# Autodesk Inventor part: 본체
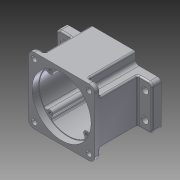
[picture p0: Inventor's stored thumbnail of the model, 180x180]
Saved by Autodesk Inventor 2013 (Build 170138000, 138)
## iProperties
Created: 2015-07
Part Number: 본체
Material: 알루미늄 6061
Document SubType Name: Modeling
Designer: user
Density: 2.71 g/cm^3
Mass: 705.328 g
Surface Area: 672.952 cm^2
Volume: 260.268 cm^3
Author: user
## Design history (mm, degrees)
sketch "스케치1"
  geometry: L1 (-45, 45)-(45, 45); L2 (45, 45)-(45, -45); L3 (45, -45)-(-45, -45); L4 (-45, -45)-(-45, 45); L5 (-45, 45)-(45, -45); L6 (45, 45)-(-45, -45); 1 further point
  constraints: 12 end point, 2 midpoint, 2 parallel, 1 horizontal, 1 perpendicular
  dimensions: "d0" = 90 distance of L2.end L3.end; "d1" = 90 distance of L1.end L2.end
extrude "돌출1" new body sketch "스케치1" distance "d2" = 58; taper "d3" = 0 deg
fillet "모깎기1" dims "d4" = 8
sketch "스케치3"
  geometry: L1 (-37, -45)-(37, -45) reference; L2 (45, -37)-(45, 37) reference; L3 (37, 45)-(-37, 45) reference; L4 (-45, 37)-(-45, -37) reference; L5 (-30, -45)-(30, -45); L6 (30, -45)-(30, 45); L7 (30, 45)-(-30, 45); L8 (-30, 45)-(-30, -45); L9 (-30, -45)-(30, 45); L10 (30, -45)-(-30, 45); L11 (-45, -30)-(45, -30); L12 (45, -30)-(45, 30); L13 (45, 30)-(-45, 30); L14 (-45, 30)-(-45, -30); L15 (-45, -30)-(45, 30); L16 (45, -30)-(-45, 30); A1 r 8 centre (-37, -37) between (-45, -37) and (-37, -45) reference; A2 r 8 centre (37, -37) between (37, -45) and (45, -37) reference; A3 r 8 centre (37, 37) between (45, 37) and (37, 45) reference; A4 r 8 centre (-37, 37) between (-37, 45) and (-45, 37) reference; 1 further point
  constraints: 24 end point, 4 midpoint, 4 parallel, 2 horizontal, 2 perpendicular
  dimensions: "d9" = 60 distance of L7.end L6.end; "d10" = 90 distance of L6.end L5.end; "d11" = 90 distance of L13.end L12.end; "d12" = 60 distance of L12.end L11.end
extrude "돌출2" cut sketch "스케치3" distance "d13" = 51; taper "d14" = 0 deg
sketch "스케치4"
  geometry: L1 (30, -45)-(-30, -45); L2 (-30, -45)-(-30, 45); L3 (-30, 45)-(30, 45); L4 (30, 45)-(30, -45); L5 (30, -45)-(-30, 45); L6 (-30, -45)-(30, 45); L7 (-65, -30)-(65, -30); L8 (65, -30)-(65, 30); L9 (65, 30)-(-65, 30); L10 (-65, 30)-(-65, -30); L11 (-65, -30)-(65, 30); L12 (65, -30)-(-65, 30); 1 further point
  constraints: 24 end point, 4 midpoint, 4 parallel, 2 horizontal, 2 perpendicular
  dimensions: "d15" = 130 distance of L9.end L8.end; "d16" = 60 distance of L8.end L7.end
extrude "돌출3" join sketch "스케치4" distance "d17" = 12; taper "d18" = 0 deg
fillet "모깎기2" dims "d19" = 5
sketch "스케치5"
  geometry: A1 r 8 centre (-37, 37) between (-37, 45) and (-45, 37) reference; A2 r 8 centre (-37, -37) between (-45, -37) and (-37, -45) reference; A3 r 8 centre (37, -37) between (37, -45) and (45, -37) reference; A4 r 8 centre (37, 37) between (45, 37) and (37, 45) reference; 1 further point
hole "구멍1" sketch "스케치5" at (37, 37), (37, -37), (-37, -37), (-37, 37) diameter "d20" = 7; stored, may be unused: countersink angle "d24" = 82 deg, drill point angle "d26" = 118 deg; dims "d21" = 6, "d22" = 3.023, "d23" = 2, "d25" = 8
fillet "모깎기3" dims "d27" = 5
fillet "모깎기5" dims "d29" = 2
sketch "스케치6"
  geometry: L1 (-55, -17.5)-(55, -17.5); L2 (55, -17.5)-(55, 17.5); L3 (55, 17.5)-(-55, 17.5); L4 (-55, 17.5)-(-55, -17.5); L5 (-55, -17.5)-(55, 17.5); L6 (55, -17.5)-(-55, 17.5); 1 further point
  constraints: 12 end point, 2 midpoint, 2 parallel, 1 horizontal, 1 perpendicular
  dimensions: "d30" = 110 distance of L3.end L2.end; "d31" = 35 distance of L2.end L1.end
hole "구멍2" sketch "스케치6" at (-55, -17.5), (-55, 17.5), (55, -17.5), (55, 17.5) diameter "d32" = 9; stored, may be unused: countersink angle "d36" = 82 deg, drill point angle "d38" = 118 deg; dims "d33" = 6, "d34" = 3.023, "d35" = 2, "d37" = 8
sketch "스케치7"
  geometry: C1 r 40 at (0, 0); 1 further point
  constraints: 1 centre point, 1 coincident
  dimensions: "d39" = 80 diameter of C1
extrude "돌출4" cut sketch "스케치7" distance "d40" = 9; taper "d41" = 0 deg
sketch "스케치8"
  geometry: C1 r 40 at (0, 0) reference; C2 r 39 at (0, 0)
  constraints: 1 centre point, 1 coincident
  dimensions: "d42" = 78 diameter of C2
extrude "돌출5" cut sketch "스케치8" distance "d43" = 52; taper "d44" = 0 deg
sketch "스케치9"
  geometry: L1 (0, 0)-(0, 11); L2 (0, 0)-(0, -20); C1 r 39 at (0, 0) reference; A1 r 20.5 centre (0, 11) between (7.402, -8.117) and (-7.402, -8.117); A2 r 14 centre (0, -20) between (-7.402, -8.117) and (7.402, -8.117)
  constraints: 4 end point, 4 point on circle, 2 centre point, 2 coincident, 1 collinear, 1 vertical
  dimensions: "d45" = 11 distance of L1.start L1.end; "d46" = 41 diameter of A1; "d47" = 20 distance of L1.start L2.end; "d48" = 28 diameter of A2
extrude "돌출6" join sketch "스케치9" distance "d49" = 7; taper "d50" = 0 deg
fillet "모깎기6" dims "d51" = 3
sketch "스케치10"
  geometry: C1 r 17.5 at (0, 11); C2 r 11 at (0, -20); A1 r 14 centre (0, -20) between (-10.493, -10.732) and (10.493, -10.732) reference; A2 r 20.5 centre (0, 11) between (11.115, -6.225) and (-11.115, -6.225) reference; 1 further point
  constraints: 2 centre point, 2 coincident
  dimensions: "d52" = 35 diameter of C1; "d53" = 22 diameter of C2
extrude "돌출7" cut sketch "스케치10" distance "d54" = 10; taper "d55" = 0 deg
extrude "돌출8" cut sketch "스케치10" distance "d56" = 7; taper "d57" = 0 deg
sketch "스케치11"
  geometry: C1 r 17.5 at (0, 0) reference; C2 r 12.5 at (0, 0); 1 further point
  constraints: 1 centre point, 1 coincident
  dimensions: "d58" = 25 diameter of C2
extrude "돌출9" cut sketch "스케치11" distance "d59" = 5; taper "d60" = 0 deg
sketch "스케치12"
  geometry: C1 r 11 at (0, 0) reference; C2 r 9.5 at (0, 0); 1 further point
  constraints: 1 centre point, 1 coincident
  dimensions: "d61" = 19 diameter of C2
extrude "돌출10" cut sketch "스케치12" distance "d62" = 1; taper "d63" = 0 deg
fillet "모깎기7" dims "d64" = 2
fillet "모깎기8" dims "d65" = 0.3
fillet "모깎기9" dims "d66" = 0.3
chamfer "모따기1" distance "d67" = 1; stored, may be unused: second distance "d68" = 2, angle "d69" = 45 deg
sketch "스케치13"
  geometry: L1 (30, 35)-(30, 45) reference; L2 (0, 0)-(0, -11); C1 r 25 at (0, -11); 1 further point
  constraints: 2 end point, 1 centre point, 1 coincident, 1 parallel
  dimensions: "d71" = 11 distance of L2.start L2.end; "d72" = 50 diameter of C1
extrude "돌출11" join sketch "스케치13" distance "d73" = 7; taper "d74" = 0 deg
sketch "스케치14"
  geometry: C1 r 25 at (0, 0) reference; C2 r 16 at (0, 0); 1 further point
  constraints: 1 centre point, 1 coincident
  dimensions: "d75" = 32 diameter of C2
extrude "돌출12" cut sketch "스케치14" distance "d76" = 8; taper "d77" = 0 deg
chamfer "모따기2" distance "d78" = 1; stored, may be unused: second distance "d79" = 2, angle "d80" = 45 deg
fillet "모깎기10" dims "d81" = 2
fillet "모깎기11" dims "d82" = 0.3
sketch "스케치15"
  geometry: L1 (0, 0)-(43.477, 43.477); L2 (0, 0)-(61.486, 0); C1 r 40 at (0, 0) reference; C2 r 4 at (24.749, 24.749); A1 r 39 centre (0, 0) between (21.134, 32.777) and (32.777, 21.134) reference; A2 r 35 centre (0, 0) between (24.749, 24.749) and (21.762, 27.412); A3 r 3.5 centre (29.836, 19.238) between (32.777, 21.134) and (27.412, 21.762); A4 r 3.5 centre (19.238, 29.836) between (21.762, 27.412) and (21.134, 32.777)
  constraints: 9 point on circle, 4 centre point, 4 end point, 2 tangent, 1 coincident, 1 equal length, 1 horizontal, 1 point on line, 1 symmetric about line, 1 other
  dimensions: "d83" = 70 diameter of A2; "d84" = 45 deg angle of L2 L1; "d85" = 8 diameter of C2; "d86" = 7 diameter of A3
extrude "돌출13" join sketch "스케치15" stored distance "d87" = 8; taper "d88" = 0 deg
fillet "모깎기12" dims "d92" = 2
sketch "스케치16"
  geometry: A1 r 4 centre (24.749, 24.749) between (21.763, 27.411) and (27.411, 21.763) reference; A2 r 4 centre (24.749, -24.749) between (27.411, -21.763) and (21.763, -27.411) reference; A3 r 4 centre (-24.749, -24.749) between (-21.763, -27.411) and (-27.411, -21.763) reference; A4 r 4 centre (-24.749, 24.749) between (-27.411, 21.763) and (-21.763, 27.411) reference
hole "구멍3" sketch "스케치16" at (-24.749, 24.749), (24.749, 24.749), (24.749, -24.749), (-24.749, -24.749) diameter "d93" = 3.459; stored, may be unused: countersink angle "d97" = 82 deg, drill point angle "d99" = 118 deg; dims "d94" = 12, "d95" = 3.023, "d96" = 2, "d98" = 15
sketch "스케치17"
  geometry: L1 (30, 45)-(-30, 45) reference; L2 (30, 35)-(30, 45) reference; L3 (0, 45)-(0, 30); 5 further points
  constraints: 2 end point, 1 coincident, 1 midpoint, 1 parallel, 1 other
  dimensions: "d101" = 15 distance of L3.start L3.end
feature "엠보싱1" sketch "스케치17" dims "d102" = 0.5, "d103" = 0
fillet "모깎기14" dims "d104" = 2
fillet "모깎기19" dims "d109" = 2
fillet "모깎기20" dims "d110" = 2
node "솔리드1"
pattern_circular "원형 패턴1" dims angle "d90" = 360 deg
